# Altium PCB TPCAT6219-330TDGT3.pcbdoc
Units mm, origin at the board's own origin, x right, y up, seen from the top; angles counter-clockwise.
Board outline 16.03 x 16.3 mm, 2 copper layers (Top Layer, Bottom Layer), stack 0 mm thick; 1 components, 0 nets, 5 pads, 0 vias.
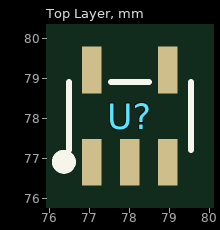
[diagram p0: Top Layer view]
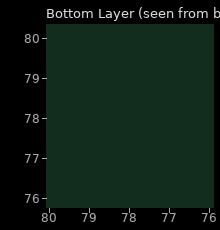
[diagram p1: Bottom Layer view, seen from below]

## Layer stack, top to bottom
Top Layer: signal copper (thickness not stored)
Bottom Layer: signal copper (thickness not stored)

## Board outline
85.877,69.85 69.85,69.85 69.85,86.154 85.877,86.154

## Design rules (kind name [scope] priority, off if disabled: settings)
PasteMaskExpansion "Paste Mask Expansion" [All] p1: expansion=0
SolderMaskExpansion "Solder Mask Expansion" [IsVia] p1: expansion=-25.4 istentingtop=TRUE
SolderMaskExpansion "Solder Mask Expansion" [All] p2: expansion=0.051 istentingtop=FALSE

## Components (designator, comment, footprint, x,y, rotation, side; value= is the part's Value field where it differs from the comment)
U? "TPCAT6219-330TDGT3" SOT-23-5_L3.0-W1.7-P0.95-LS2.8-BL 78.001,78.063 r0 top

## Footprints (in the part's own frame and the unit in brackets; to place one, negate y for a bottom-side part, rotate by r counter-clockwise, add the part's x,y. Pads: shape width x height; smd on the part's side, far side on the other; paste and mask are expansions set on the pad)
SOT-23-5_L3.0-W1.7-P0.95-LS2.8-BL [mm]
  rect 0.49x1.157 smd: 1(-0.95,-1.154) 2(0,-1.154) 3(0.95,-1.154)
  rect 0.49x1.175 smd: 4(0.95,1.154) 5(-0.95,1.154)
  silkscreen extent -1.8,-1.29 1.53,0.85

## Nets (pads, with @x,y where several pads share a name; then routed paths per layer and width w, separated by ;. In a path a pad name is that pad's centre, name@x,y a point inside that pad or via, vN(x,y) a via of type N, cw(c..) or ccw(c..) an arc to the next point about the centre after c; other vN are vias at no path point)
pads on no net: U?.1 U?.2 U?.3 U?.4 U?.5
